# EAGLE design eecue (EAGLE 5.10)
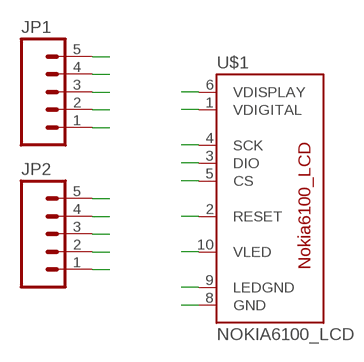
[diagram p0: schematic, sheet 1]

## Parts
JP1  M05LOCK_LONGPADS  [1X05_LOCK_LONGPADS]
JP2  M05LOCK_LONGPADS  [1X05_LOCK_LONGPADS]
U$1  NOKIA6100_LCD  [NOKIA6100_LCD]

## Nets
CS: JP1.5 U$1.5(CS)
DIO: JP1.3 U$1.3(DIO)
GND: JP2.3 U$1.8(GND)
LEDGND: JP2.4 U$1.9(LEDGND)
N$9: JP2.2
RESET: JP1.2 U$1.2(RESET)
SCK: JP1.4 U$1.4(SCK)
VDIGITAL: JP1.1 U$1.1(VDIGITAL)
VDISPLAY: JP2.1 U$1.6(VDISPLAY)
VLED: JP2.5 U$1.10(VLED)

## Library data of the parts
JP1 JP2 = SparkFun:M05: Header 5 Standard 5-pin 0.1" header. Use with straight break away headers (SKU : PRT-00116), right angle break away headers (PRT-00553), swiss pins (PRT-00743), machine pins (PRT-00117), and female headers (PRT-00115). Molex polarized connector foot print use with SKU : PRT-08230 with associated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
U$1 = SparkFun:NOKIA6100_LCD: Nokia 6100 Color LCD Schematic element and footprint production proven but could use some touching up. Spark Fun Electronics SKU : LCD-00569. Mating SMD connector : LCD-00570

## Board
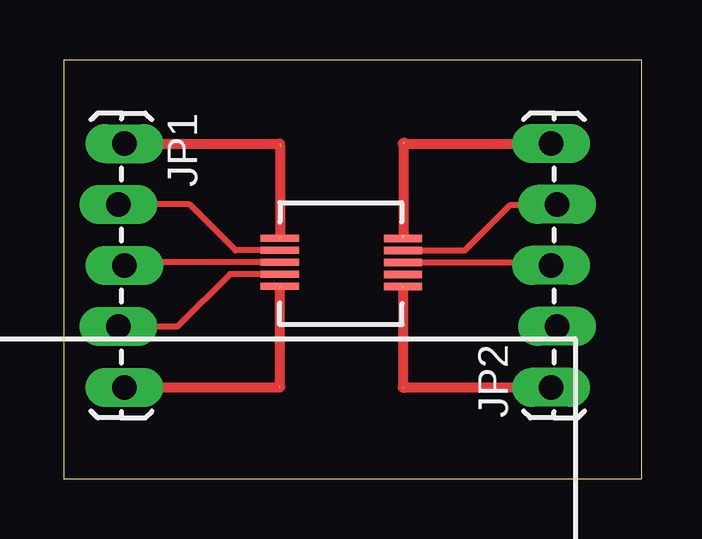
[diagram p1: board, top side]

Size 24.11 x 17.45 mm. Coordinates in mm from the lower left corner, seen from the top.
Outline: 0,0 24.11,0 24.11,17.45 0,17.45 0,0
Copper layers (1*16): Top 0.0356mm / dielectric 1.5011mm / Bottom 0.0356mm
Design rules "SparkFun-mod": minimum track width 8mil, minimum drill 20mil, track to track 12mil, track to pad 12mil, pad to pad 8mil, via to via 8mil, smd to smd 8mil, copper to edge 12mil, drill to drill 8mil, minimum pad ring 12mil, minimum via ring 10mil, stop-mask expansion 4mil, vias tented up to drill 25mil, thermal gap 10mil

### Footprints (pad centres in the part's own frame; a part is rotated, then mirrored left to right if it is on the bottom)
1X05_LOCK_LONGPADS = drill 1.016 long: 1 0,0; 2 2.54,-0.254; 3 5.08,0; 4 7.62,-0.254; 5 10.16,0
NOKIA6100_LCD = smd 1.6 x 0.3: 1 24.255,44.311; 2 24.255,43.811; 3 24.255,43.311; 4 24.255,42.811; 5 24.255,42.311; 6 29.389,42.303; 7 29.389,42.803; 8 29.389,43.303; 9 29.389,43.803; 10 29.389,44.303

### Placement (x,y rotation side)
JP1  2.54,13.97 270 top
JP2  20.32,3.81 90 top
U$1  -15.24,-34.29 0 top

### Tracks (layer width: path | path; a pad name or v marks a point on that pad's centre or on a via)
CS  (2 unrouted)
  Top 0.406: JP1.5 9.02,3.81 | 8.99,7.93 9.03,7.93 9.03,3.83
DIO
  Top 0.254: U$1.3 2.67,9.02
  Top 0.406: 2.67,9.02 JP1.3
GND
  Top 0.254: U$1.8 20.2,9.01 JP2.3
LEDGND
  Top 0.203: 20.56,11.42 JP2.4
  Top 0.254: U$1.9 16.73,9.51 18.64,11.42 20.56,11.42
RESET
  Top 0.254: U$1.2 7.16,9.52 5.26,11.43 JP1.2
SCK
  Top 0.203: 6.94,8.52 6.93,8.53
  Top 0.254: JP1.4 4.75,6.35 6.93,8.53 | U$1.4 6.94,8.52
VDIGITAL  (2 unrouted)
  Top 0.406: JP1.1 9.02,13.97 | 8.98,13.84 9.04,13.84 9.04,10.09
VDISPLAY  (2 unrouted)
  Top 0.406: 14.15,3.81 JP2.1 | 14.14,7.95 14.18,7.95 14.18,3.78
VLED  (2 unrouted)
  Top 0.406: 14.15,13.97 JP2.5 | 14.19,10.15 14.19,14.02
